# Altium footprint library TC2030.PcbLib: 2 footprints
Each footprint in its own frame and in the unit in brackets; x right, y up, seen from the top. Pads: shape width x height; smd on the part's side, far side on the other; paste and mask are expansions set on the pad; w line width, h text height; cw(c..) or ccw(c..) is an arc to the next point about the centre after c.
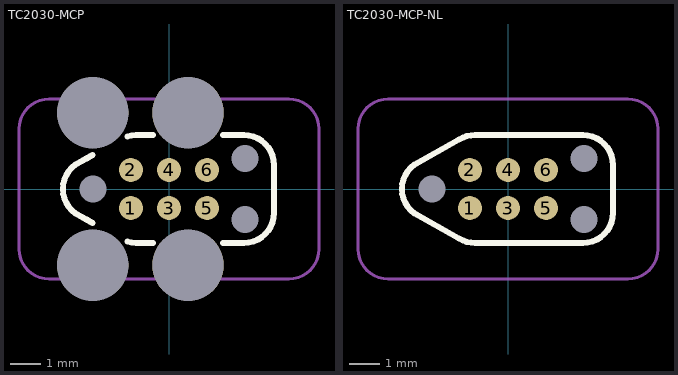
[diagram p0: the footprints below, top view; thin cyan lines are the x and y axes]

## TC2030-MCP [mm] "Conector ICD en placa"
height 8
pads (13):
  round 0.8 smd paste-0.4: 1(-1.27,-0.635) 2(-1.27,0.635) 3(0,-0.635) 4(0,0.635) 5(1.27,-0.635) 6(1.27,0.635)
  round 2.375 hole 2.375 unplated mask+0: ""(-2.54,-2.54) ""(-2.54,2.54) ""(0.635,-2.54) ""(0.635,2.54)
  round 0.85 hole 0.9 unplated mask+0: ""(-2.54,0) ""(2.54,-1.016) ""(2.54,1.016)
Top Overlay:
  lines w0.2: -2.556,-1.128 -2.741,-1.024 -3.111,-0.816 cw(c-2.544,0) -3.111,0.816 -2.741,1.024 -2.556,1.128 ; -1.387,-1.758 ccw(c-1.1,-0.8) -1.1,-1.8 -0.54,-1.8 ; -1.387,1.758 cw(c-1.1,0.8) -1.1,1.8 -0.54,1.8 ; 1.8,-1.8 2.5,-1.8 ccw(c2.5,-0.8) 3.5,-0.8 3.5,0.8 ccw(c2.5,0.8) 2.5,1.8 1.8,1.8
Mechanical 15:
  lines w0.1: -5,-2 ccw(c-4,-2) -4,-3 4,-3 ccw(c4,-2) 5,-2 5,2 ccw(c4,2) 4,3 -4,3 ccw(c-4,2) -5,2 -5,-2
3D body: height 0, standoff 0, extent -3.547,-1.809 3.509,1.809

## TC2030-MCP-NL [mm] "Conector ICD en placa"
height 8
pads (9):
  round 0.8 smd paste-0.4: 1(-1.27,-0.635) 2(-1.27,0.635) 3(0,-0.635) 4(0,0.635) 5(1.27,-0.635) 6(1.27,0.635)
  round 0.85 hole 0.9 unplated mask+0: ""(-2.54,0) ""(2.54,-1.016) ""(2.54,1.016)
Top Overlay:
  lines w0.2: -3.111,-0.816 cw(c-2.544,0) -3.111,0.816 -1.63,1.648 cw(c-1.1,0.8) -1.1,1.8 2.5,1.8 cw(c2.5,0.8) 3.5,0.8 3.5,-0.8 cw(c2.5,-0.8) 2.5,-1.8 -1.1,-1.8 cw(c-1.1,-0.8) -1.63,-1.648 -3.111,-0.816
Mechanical 15:
  lines w0.1: -5,-2 ccw(c-4,-2) -4,-3 4,-3 ccw(c4,-2) 5,-2 5,2 ccw(c4,2) 4,3 -4,3 ccw(c-4,2) -5,2 -5,-2
3D body: height 0, standoff 0, extent -3.547,-1.809 3.509,1.809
